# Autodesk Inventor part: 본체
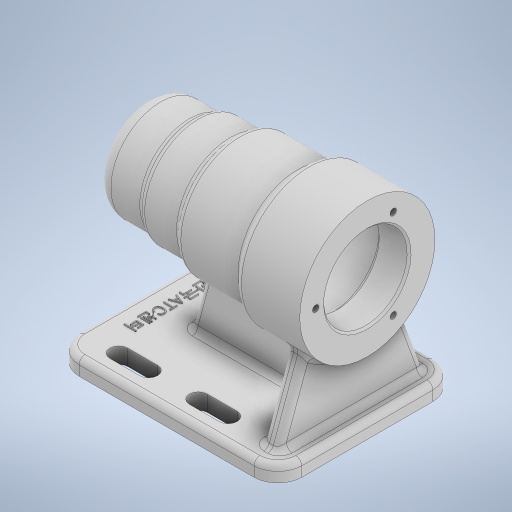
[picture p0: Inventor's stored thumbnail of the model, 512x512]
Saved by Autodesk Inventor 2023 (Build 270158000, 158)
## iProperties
Created: 2022-07
Part Number: 본체
Material: 일반
Document SubType Name: Modeling
Designer: owner
Density: 1 g/cm^3
Appearance: 기본값
Author: owner
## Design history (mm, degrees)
sketch "스케치1"
  geometry: L1 (44, -45)-(-44, -45); L2 (-56, -33)-(-56, 33); L3 (-44, 45)-(44, 45); L4 (56, 33)-(56, -33); L5 (56, -45)-(-56, 45); L6 (-56, -45)-(56, 45); L7 (36, 33)-(21, 33); L8 (36, 37.5)-(21, 37.5); L9 (21, 28.5)-(36, 28.5); L10 (-4, 33)-(-19, 33); L11 (-4, 37.5)-(-19, 37.5); L12 (-19, 28.5)-(-4, 28.5); L13 (56, 0)-(-56, 0); L14 (21, -28.5)-(36, -28.5); L15 (36, -37.5)-(21, -37.5); L16 (-19, -28.5)-(-4, -28.5); L17 (-4, -37.5)-(-19, -37.5); A1 r 12 centre (44, 33) between (56, 33) and (44, 45); A2 r 12 centre (-44, 33) between (-44, 45) and (-56, 33); A3 r 12 centre (-44, -33) between (-56, -33) and (-44, -45); A4 r 12 centre (44, -33) between (44, -45) and (56, -33); A5 r 4.5 centre (36, 33) between (36, 28.5) and (36, 37.5); A6 r 4.5 centre (21, 33) between (21, 37.5) and (21, 28.5); A7 r 4.5 centre (-4, 33) between (-4, 28.5) and (-4, 37.5); A8 r 4.5 centre (-19, 33) between (-19, 37.5) and (-19, 28.5); A9 r 4.5 centre (36, -33) between (36, -37.5) and (36, -28.5); A10 r 4.5 centre (21, -33) between (21, -28.5) and (21, -37.5); A11 r 4.5 centre (-4, -33) between (-4, -37.5) and (-4, -28.5); A12 r 4.5 centre (-19, -33) between (-19, -28.5) and (-19, -37.5); 3 further points
  constraints: 38 end point, 24 point on circle, 16 tangent, 12 centre point, 12 symmetric about line, 8 point on line, 6 midpoint, 4 parallel, 3 equal radius, 3 horizontal, 1 collinear, 1 perpendicular, 4 other
  dimensions: "d0" = 112 distance of L5.end L6.end; "d1" = 90 distance of L6.start L5.end; "d2" = 12 radius of A1; "d3" = 15 distance of L7.start L7.end; "d4" = 9 diameter of A6; "d5" = 33 distance from line of point (0, 0) L7; "d6" = 20 distance from line of L4 L7.start; "d7" = 15 distance of L10.start L10.end; "d8" = 9 diameter of A8; "d9" = 25 distance of L10.start L7.end
extrude "돌출1" new body sketch "스케치1" distance "d10" = 8; taper "d11" = 0 deg
fillet "모깎기1" dims "d12" = 3
sketch "스케치2"
  geometry: L1 (-56, 70)-(56, 70); L2 (56, 0)-(44, 0) reference; L3 (-44, 0)-(44, 0) reference; L4 (-56, 70)-(-56, 87); L5 (-48, 95)-(-33.472, 95); L6 (-32, 95)-(-32, 94); L7 (-29, 97)-(-13, 97); L8 (-10, 100)-(-10, 100); L9 (-7.804, 100)-(21, 100); L10 (24, 103)-(24, 104); L11 (26.657, 104)-(56, 104); L12 (56, 104)-(56, 91); L13 (56, 91)-(41, 91); L14 (41, 91)-(41, 91); L15 (38, 94)-(-10, 94); L16 (-13, 91)-(-13, 91); L17 (-13, 91)-(-24.7, 91); L18 (-25, 90.7)-(-25, 87.5); L19 (-25, 87.5)-(-42.7, 87.5); L20 (-43, 87.2)-(-43, 86); L21 (-43, 86)-(-46.7, 86); L22 (-47, 85.7)-(-47, 80.5); L23 (-47, 80.5)-(-47, 80.5); L24 (-50, 77.5)-(-50, 70); A1 r 0.3 centre (-46.7, 85.7) between (-46.7, 86) and (-47, 85.7); A2 r 0.3 centre (-42.7, 87.2) between (-42.7, 87.5) and (-43, 87.2); A3 r 0.3 centre (-24.7, 90.7) between (-24.7, 91) and (-25, 90.7); A4 r 8 centre (-48, 87) between (-48, 95) and (-56, 87); A5 r 3 centre (-29, 94) between (-29, 97) and (-31.236, 96); A6 r 3 centre (-33.472, 98) between (-33.472, 95) and (-31.236, 96); A7 r 3 centre (-13, 100) between (-13, 97) and (-10.402, 98.5); A8 r 3 centre (-7.804, 97) between (-7.804, 100) and (-10.402, 98.5); A9 r 3 centre (21, 103) between (21, 100) and (23.828, 102); A10 r 3 centre (26.657, 101) between (26.657, 104) and (23.828, 102); A11 r 3 centre (-10, 91) between (-10, 94) and (-13, 91); A12 r 3 centre (38, 91) between (41, 91) and (38, 94); A13 r 3 centre (-47, 77.5) between (-47, 80.5) and (-50, 77.5); 16 further points
  constraints: 44 end point, 29 point on circle, 26 tangent, 24 point on line, 18 perpendicular, 13 centre point, 9 equal radius, 2 horizontal, 2 midpoint, 1 vertical, 1 vertical alignment
  dimensions: "d13" = 112 distance of L1.start L1.end; "d14" = 70 distance between parallel lines of L2 L1; "d15" = 25 distance of L1.start point (-56, 95); "d16" = 24 distance of point (-56, 95) L6.start; "d17" = 2 distance of L6.start point (-32, 97); "d18" = 22 distance of point (-32, 97) point (-10, 97); "d19" = 3 distance of point (-10, 97) L8.end; "d20" = 34 distance of L8.end point (24, 100); "d21" = 4 distance of point (24, 100) L10.end; "d22" = 32 distance of L10.end L11.end; "d23" = 13 distance of L11.end L12.end; "d24" = 15 distance of L12.end L13.end; "d25" = 3 distance of L13.end point (41, 94); "d27" = 54 distance of point (41, 94) point (-13, 94); "d28" = 3 distance of point (-13, 94) L16.end; "d29" = 12 distance of L16.end point (-25, 91); "d30" = 3.5 distance of point (-25, 91) L18.end; "d31" = 18 distance of L18.end point (-43, 87.5); "d32" = 1.5 distance of point (-43, 87.5) L20.end; "d33" = 4 distance of L20.end point (-47, 86); "d34" = 5.5 distance of point (-47, 86) L22.end; "d35" = 3 distance of L22.end point (-50, 80.5); "d36" = 10.5 distance of point (-50, 80.5) L24.end; "d37" = 0.3 radius of A1; "d38" = 8 radius of A4; "d39" = 3 radius of A5; "d40" = 3 radius of A10 (derived)
revolve "회전1" sketch "스케치2" stored, may be unused: angle "d41" = 90 deg
chamfer "모따기1" distance "d42" = 1; stored, may be unused: second distance "d43" = 2, angle "d44" = 45 deg
sketch "스케치3" dims "d52" = 52
  geometry: C1 r 7.5 at (0, 0) reference; 3 further points
  constraints: 2 horizontal alignment, 1 coincident, 2 other
hole "구멍1" sketch "스케치3" at (-26, 0) diameter "d45" = 3.242; stored, may be unused: countersink angle "d49" = 90 deg, drill point angle "d51" = 118 deg; dims "d46" = 8, "d47" = 52, "d48" = 18, "d50" = 11
node "작업 평면1"
sketch "스케치4"
  geometry: L1 (9.591, 45.342)-(-4, 8); L2 (-9, 8)-(0, 8) reference; L3 (-12, 0)-(-12, 5) reference; L4 (33, 0)-(33, 70); L5 (56.409, 45.342)-(70, 8); L6 (0, 8)-(66, 8) reference; L7 (61.5, 8)-(70.5, 8) reference; 1 further point
  constraints: 6 end point, 2 symmetric about line, 1 point on line, 1 vertical, 2 other
  dimensions: "d57" = 110 deg angle of L2 L1; "d58" = 8 distance from line of L3 L1.end
extrude "돌출2" join sketch "스케치4" distance "d59" = 8; taper "d60" = 0 deg
sketch "스케치5"
  geometry: L1 (-29, 43)-(-13, 43) reference; L2 (-19.622, 43)-(-29, 8); L3 (-21, 8)-(-36, 8) reference; L4 (48, 8)-(48, 45.342) reference; 1 further point
  constraints: 2 end point, 2 point on line
  dimensions: "d61" = 77 distance from line of L4 L2.end; "d62" = 105 deg angle of L3 L2
feature "리브1" sketch "스케치5" dims "d63" = 1, "d64" = 8, "d65" = 0, "d66" = 0, "d67" = 1, "d68" = 1
fillet "모깎기2" dims "d69" = 3
fillet "모깎기3" dims "d70" = 3
fillet "모깎기4" dims "d71" = 3
sketch "스케치6"
  geometry: L1 (-56, 33)-(-56, -33) reference; 2 further points
  constraints: 1 horizontal alignment, 1 other
  dimensions: "d72" = 12 distance from line of L1 point (-44, 0)
feature "엠보싱1" sketch "스케치6" dims "d73" = 0.5, "d74" = 0
node "솔리드1"
pattern_circular "원형 패턴1" dims angle "d54" = 360 deg
feature "A9D066F2-1C7D-4E18-AEED-F7BC21143FA4" dims "d45" = 3.242, "d46" = 8, "d47" = 52, "d48" = 18, "d49" = 90 deg, "d50" = 11, "d51" = 118 deg
other parameters: "d56" = -8
